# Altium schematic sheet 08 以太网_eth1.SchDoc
size 297 x 209 mm
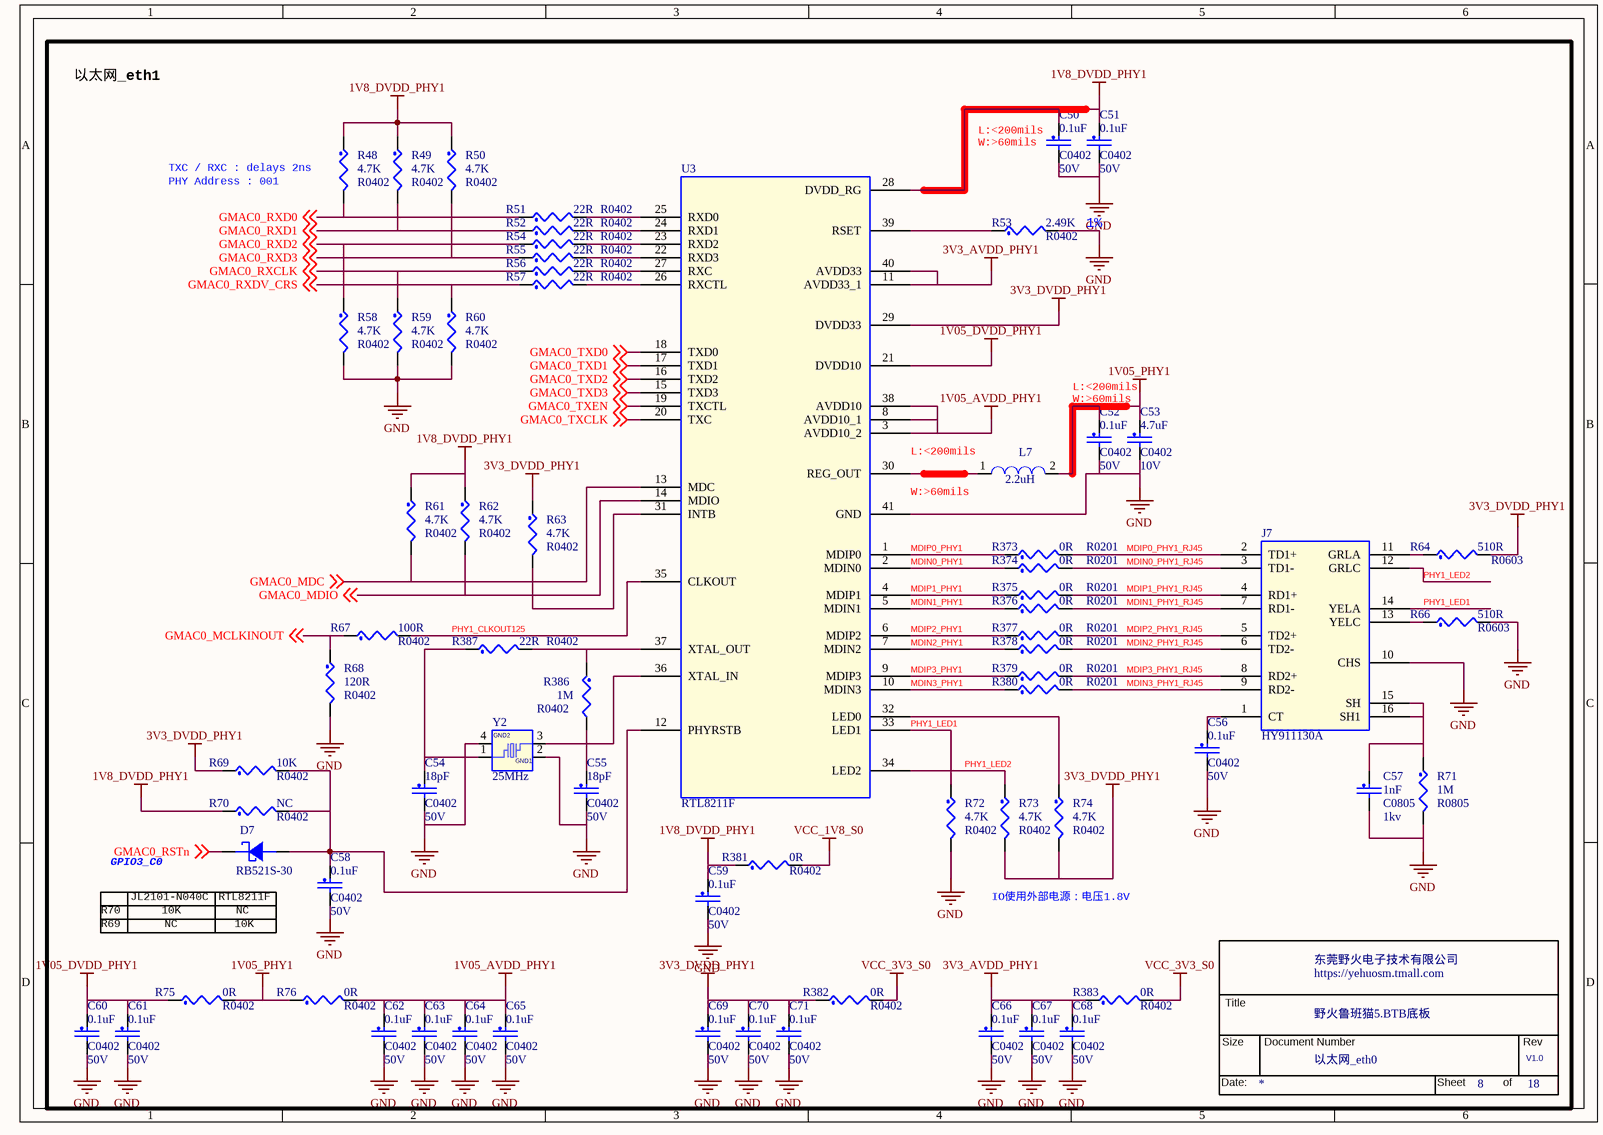
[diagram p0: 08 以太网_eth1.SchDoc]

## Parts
*  Doc: 以太网_eth0  RevCode: V1.0  Title: 野火鲁班猫5.BTB底板  OrgName: 东莞野火电子技术有限公司  Page Number: 8  Page Count: 18  (hidden comment: TitleBlock_YHSCH)  (graphical)
C50  0.1uF  Voltage: 50V  [C0402]
C51  0.1uF  Voltage: 50V  [C0402]
C52  0.1uF  Voltage: 50V  [C0402]
C53  4.7uF  Voltage: 10V  [C0402]
C54  18pF  Voltage: 50V  [C0402]
C55  18pF  Voltage: 50V  [C0402]
C56  0.1uF  Voltage: 50V  [C0402]
C57  1nF  Voltage: 1kv  [C0805]
C58  0.1uF  Voltage: 50V  [C0402]
C59  0.1uF  Voltage: 50V  [C0402]
C60  0.1uF  Voltage: 50V  [C0402]
C61  0.1uF  Voltage: 50V  [C0402]
C62  0.1uF  Voltage: 50V  [C0402]
C63  0.1uF  Voltage: 50V  [C0402]
C64  0.1uF  Voltage: 50V  [C0402]
C65  0.1uF  Voltage: 50V  [C0402]
C66  0.1uF  Voltage: 50V  [C0402]
C67  0.1uF  Voltage: 50V  [C0402]
C68  0.1uF  Voltage: 50V  [C0402]
C69  0.1uF  Voltage: 50V  [C0402]
C70  0.1uF  Voltage: 50V  [C0402]
C71  0.1uF  Voltage: 50V  [C0402]
D7  RB521S-30  [SOD523]
J7  HY911130A  [HY911130A]
L7  2.2uH  [L2520]
R48  4.7K  [R0402]
R49  4.7K  [R0402]
R50  4.7K  [R0402]
R51  22R  [R0402]
R52  22R  [R0402]
R53  2.49K  [R0402]
R54  22R  [R0402]
R55  22R  [R0402]
R56  22R  [R0402]
R57  22R  [R0402]
R58  4.7K  [R0402]
R59  4.7K  [R0402]
R60  4.7K  [R0402]
R61  4.7K  [R0402]
R62  4.7K  [R0402]
R63  4.7K  [R0402]
R64  510R  [R0603]
R66  510R  [R0603]
R67  100R  [R0402]
R68  120R  [R0402]
R69  10K  [R0402]
R70  NC  [R0402]
R71  1M  [R0805]
R72  4.7K  [R0402]
R73  4.7K  [R0402]
R74  4.7K  [R0402]
R75  0R  [R0402]
R76  0R  [R0402]
R373  0R  [R0201]
R374  0R  [R0201]
R375  0R  [R0201]
R376  0R  [R0201]
R377  0R  [R0201]
R378  0R  [R0201]
R379  0R  [R0201]
R380  0R  [R0201]
R381  0R  [R0402]
R382  0R  [R0402]
R383  0R  [R0402]
R386  1M  [R0402]
R387  22R  [R0402]
U3  RTL8211F  [qfp_40p_r]
Y2  25MHz  [3225]

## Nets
1V05_AVDD_PHY1: C62.1 C63.1 C64.1 C65.1 R76.2 U3.3(AVDD10_2) U3.8(AVDD10_1) U3.38(AVDD10)
1V05_DVDD_PHY1: C60.1 C61.1 R75.1 U3.21(DVDD10)
1V05_PHY1: C52.1 C53.1 L7.2 R75.2 R76.1
1V8_DVDD_PHY1: C50.1 C51.1 C59.1 R48.1 R49.1 R50.1 R61.1 R62.1 R70.1 R381.1 U3.28(DVDD_RG)
3V3_AVDD_PHY1: C66.1 C67.1 C68.1 R383.1 U3.11(AVDD33_1) U3.40(AVDD33)
3V3_DVDD_PHY1: C69.1 C70.1 C71.1 R63.1 R64.2 R69.1 R73.2 R74.2 R382.1 U3.29(DVDD33)
GND: C50.2 C51.2 C52.2 C53.2 C54.2 C55.2 C56.2 C57.2 C58.2 C59.2 C60.2 C61.2 C62.2 C63.2 C64.2 C65.2 C66.2 C67.2 C68.2 C69.2 C70.2 C71.2 J7.10(CHS) R53.2 R58.2 R59.2 R60.2 R66.2 R68.2 R71.2 R72.2 U3.41(GND) Y2.2(GND1) Y2.4(GND2)
VCC_1V8_S0: R381.2
VCC_3V3_S0: R382.2 R383.2
GMAC0_MCLKINOUT: R67.1 R68.1 ; off-sheet GMAC0_MCLKINOUT
GMAC0_MDC: R61.2 U3.13(MDC) ; off-sheet GMAC0_MDC
GMAC0_MDIO: R62.2 U3.14(MDIO) ; off-sheet GMAC0_MDIO
GMAC0_RSTn: D7.1 ; off-sheet GMAC0_RSTn
GMAC0_RXCLK: R56.1 R59.1 ; off-sheet GMAC0_RXCLK
GMAC0_RXD0: R48.2 R51.1 ; off-sheet GMAC0_RXD0
GMAC0_RXD1: R49.2 R52.1 ; off-sheet GMAC0_RXD1
GMAC0_RXD2: R54.1 R58.1 ; off-sheet GMAC0_RXD2
GMAC0_RXD3: R50.2 R55.1 ; off-sheet GMAC0_RXD3
GMAC0_RXDV_CRS: R57.1 R60.1 ; off-sheet GMAC0_RXDV_CRS
GMAC0_TXCLK: U3.20(TXC) ; off-sheet GMAC0_TXCLK
GMAC0_TXD0: U3.18(TXD0) ; off-sheet GMAC0_TXD0
GMAC0_TXD1: U3.17(TXD1) ; off-sheet GMAC0_TXD1
GMAC0_TXD2: U3.16(TXD2) ; off-sheet GMAC0_TXD2
GMAC0_TXD3: U3.15(TXD3) ; off-sheet GMAC0_TXD3
GMAC0_TXEN: U3.19(TXCTL) ; off-sheet GMAC0_TXEN
MDIN0_PHY1: R374.1 U3.2(MDIN0)
MDIN0_PHY1_RJ45: J7.3(TD1-) R374.2
MDIN1_PHY1: R376.1 U3.5(MDIN1)
MDIN1_PHY1_RJ45: J7.7(RD1-) R376.2
MDIN2_PHY1: R378.1 U3.7(MDIN2)
MDIN2_PHY1_RJ45: J7.6(TD2-) R378.2
MDIN3_PHY1: R380.1 U3.10(MDIN3)
MDIN3_PHY1_RJ45: J7.9(RD2-) R380.2
MDIP0_PHY1: R373.1 U3.1(MDIP0)
MDIP0_PHY1_RJ45: J7.2(TD1+) R373.2
MDIP1_PHY1: R375.1 U3.4(MDIP1)
MDIP1_PHY1_RJ45: J7.4(RD1+) R375.2
MDIP2_PHY1: R377.1 U3.6(MDIP2)
MDIP2_PHY1_RJ45: J7.5(TD2+) R377.2
MDIP3_PHY1: R379.1 U3.9(MDIP3)
MDIP3_PHY1_RJ45: J7.8(RD2+) R379.2
PHY1_CLKOUT125: R67.2 U3.35(CLKOUT)
PHY1_LED1: J7.14(YELA) R72.1 U3.33(LED1)
PHY1_LED2: J7.12(GRLC) R73.1 U3.34(LED2)
NetC54_1: C54.1 R387.1 Y2.1
NetC55_1: C55.1 R386.2 U3.36(XTAL_IN) Y2.3
NetC56_1: C56.1 J7.1(CT)
NetC57_1: C57.1 J7.15(SH) J7.16(SH1) R71.1
NetC58_1: C58.1 D7.2 R69.2 R70.2 U3.12(PHYRSTB)
NetJ7_11: J7.11(GRLA) R64.1
NetJ7_13: J7.13(YELC) R66.1
NetL7_1: L7.1 U3.30(REG_OUT)
NetR51_2: R51.2 U3.25(RXD0)
NetR52_2: R52.2 U3.24(RXD1)
NetR53_1: R53.1 U3.39(RSET)
NetR54_2: R54.2 U3.23(RXD2)
NetR55_2: R55.2 U3.22(RXD3)
NetR56_2: R56.2 U3.27(RXC)
NetR57_2: R57.2 U3.26(RXCTL)
NetR63_2: R63.2 U3.31(INTB)
NetR74_1: R74.1 U3.32(LED0)
NetR386_1: R386.1 R387.2 U3.37(XTAL_OUT)

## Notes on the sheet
- 以太网_eth1
- (near C50) L:<200mils
  W:>60mils
- PHY Address : 001
- TXC / RXC : delays 2ns
- (near R53) 1%
- L:<200mils
  W:>60mils
- L:<200mils
- W:>60mils
- GPIO3_C0
- R70
- R69
- JL2101-N040C
- 10K
- NC
- (near D7) RTL8211F
- IO使用外部电源：电压1.8V

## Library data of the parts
* = TitleBlock_YHSCH: Cage Code: 1
C50-C52 C59 C66-C68 = CAP_NP: CLASS: DISCRETE; 规格: 贴片电容0.1uF 10% 50V X5R 0402; 规格编号: 0402X104K500NT; 条码: EBF29060118; 品牌: 风华; 类别: 贴片电容0402; 规格书: 风华电容.pdf; 价格: 0.029826; 生命周期: 量产
C53 = CAP_NP: CLASS: DISCRETE; 规格: 贴片电容4.7uF 10% 10V X5R 0402; 规格编号: CC0402KRX5R6BB475; 条码: EBF29060248; 品牌: 国巨; 类别: 贴片电容0402; 规格书: 国巨-贴片电容.pdf; 价格: 0.059058; 生命周期: 量产
C54 C55 = CAP_NP: CLASS: DISCRETE; 规格: 贴片电容18pF 5% 50V C0G 0402; 规格编号: 0402CG180J500NT; 条码: EBF29060235; 品牌: 风华; 类别: 贴片电容0402; 规格书: 风华电容.pdf; 价格: 0.00515; 生命周期: 量产
C56 C58 C60-C65 C69-C71 = CAP_NP: CLASS: DISCRETE; 生命周期: 量产; 价格: 0.029826; 规格书: 风华电容.pdf; 类别: 贴片电容0402; 品牌: 风华; 条码: EBF29060118; 规格编号: 0402X104K500NT; 规格: 贴片电容0.1uF 10% 50V X5R 0402
C57 = CAP_NP: CLASS: DISCRETE; 生命周期: 量产; 价格: 0.083527; 规格书: 华新科0805系列高压贴片电容.pdf; 类别: 贴片电容0805; 品牌: 华新科; 条码: EBF29060304; 规格编号: 0805B102K102CT; 规格: 贴片电容1nF 10% 1kV X7R 0805
D7 = DIODE_SCHTKY: CLASS: IC; 生命周期: 量产; 价格: 0.06781; 规格书: 江苏长电_RB521S-30.pdf; 类别: 贴片肖特基二极管; 品牌: 江苏长电; 条码: EBFCIS221114153437; 规格: 直流反向耐压(Vr)：30V 平均整流电流(Io)：200mA 正向压降(Vf)：500mV@200mA 30V@100mA,VF=350mV@10mA
J7 = HY911130A: 规格: 屏蔽式以太网连接器RJ45 引脚数14 LED灯黄绿 1000M; 条码: EBF29040053; 品牌: 汉仁; 类别: 网口; 规格书: 汉仁_1000M_ HY911130A.pdf; 价格: 11.12; 生命周期: 量产
L7 = IND: CLASS: DISCRETE; 规格: 功率电感2.2uH 2.2uH ±20% 2.06A 85mΩ; 规格编号: WIP252012P-2R2ML; 条码: EBFCIS220927171910; 品牌: 佳邦; 类别: 贴片电感2520; 规格书: 佳邦_ WIP252012P-2R2ML.pdf; 价格: 0.129914; 生命周期: 量产
R48-R50 R58-R63 R72-R74 = RES: CLASS: DISCRETE; 规格: 贴片电阻4.7K 1% 1/16W 0402; 规格编号: RI0402L4701FT; 条码: EBF29070047; 品牌: 合科泰; 类别: 贴片电阻0402; 规格书: 合科泰-RI系列电阻.pdf; 生命周期: 量产
R51 R52 R54-R57 = RES: CLASS: DISCRETE; 生命周期: 量产; 规格书: 合科泰-RI系列电阻.pdf; 类别: 贴片电阻0402; 品牌: 合科泰; 条码: EBF29070181; 规格编号: RI0402L22R0FT; 规格: 贴片电阻22R 1% 1/16W 0402
R53 = RES: CLASS: DISCRETE; 价格: 0.004709; 生命周期: 量产; 规格书: 厚声-无铅厚膜电阻.pdf; 类别: 贴片电阻0402; 品牌: 厚声; 条码: EBF29070292; 规格编号: 0402WGF2491TCE; 规格: 贴片电阻2.49K 1% 1/16W 0402
R64 = RES: CLASS: DISCRETE; 规格: 贴片电阻510R 1% 1/10W 0603; 规格编号: RI0603L5100FT; 条码: EBF29070091; 品牌: 合科泰; 类别: 贴片电阻0603; 规格书: 合科泰-RI系列电阻.pdf; 生命周期: 量产
R66 = RES: CLASS: DISCRETE; 生命周期: 量产; 规格书: 合科泰-RI系列电阻.pdf; 类别: 贴片电阻0603; 品牌: 合科泰; 条码: EBF29070091; 规格编号: RI0603L5100FT; 规格: 贴片电阻510R 1% 1/10W 0603
R67 = RES: CLASS: DISCRETE; 生命周期: 量产; 规格书: 合科泰-RI系列电阻.pdf; 类别: 贴片电阻0402; 品牌: 合科泰; 条码: EBF29070053; 规格编号: RI0402L1000FT; 规格: 贴片电阻100R 1% 1/16W 0402
R68 = RES: CLASS: DISCRETE; 生命周期: 量产; 规格书: 厚声-无铅厚膜电阻.pdf; 类别: 贴片电阻0402; 品牌: 厚声; 条码: EBF29070275; 规格编号: 0402WGF1200TCE; 规格: 贴片电阻120R 1% 1/16W 0402; 价格: 0.002198
R69 = RES: CLASS: DISCRETE; 生命周期: 量产; 价格: 0.002773; 规格书: 厚声-无铅厚膜电阻.pdf; 类别: 贴片电阻0402; 品牌: 厚声; 条码: EBF29070046; 规格编号: 0402WGF1002TCE; 规格: 贴片电阻10K 1% 1/16W 0402
R70 = RES: CLASS: DISCRETE; 规格: 贴片电阻NC 预留; 条码: EBF29070087; 类别: 贴片电阻0402
R71 = RES: CLASS: DISCRETE; 生命周期: 量产; 价格: 0.02396; 规格书: YAGEO国巨厚膜无铅电阻.pdf; 类别: 贴片电阻0805; 品牌: 国巨; 条码: EBF29070294; 规格编号: AC0805FR-071ML; 规格: 贴片电阻1M 1% 1/8W 0805
R75 R76 R381 R382 = RES: CLASS: DISCRETE; 生命周期: 量产; 规格书: 合科泰-RI系列电阻.pdf; 类别: 贴片电阻0402; 品牌: 合科泰; 条码: EBF29070049; 规格编号: RI0402L000FT; 规格: 贴片电阻0R 1% 1/16W 0402
R373-R380 = RES: CLASS: DISCRETE; 规格: 贴片电阻0R 1% 1/20W 0201; 规格编号: RI0201L0000FT; 条码: EBF29070164; 品牌: 合科泰; 类别: 贴片电阻0201; 规格书: 合科泰-RI系列电阻.pdf; 生命周期: 量产
R383 = RES: CLASS: DISCRETE; 规格: 贴片电阻0R 1% 1/16W 0402; 规格编号: RI0402L000FT; 条码: EBF29070049; 品牌: 合科泰; 类别: 贴片电阻0402; 规格书: 合科泰-RI系列电阻.pdf; 生命周期: 量产
R386 = RES: CLASS: DISCRETE; 生命周期: 量产; 规格书: 合科泰-RI系列电阻.pdf; 类别: 贴片电阻0402; 品牌: 厚声; 条码: EBF29070062; 规格编号: RI0402L1004FT; 规格: 贴片电阻1M 1% 1/16W 0402
R387 = RES: CLASS: DISCRETE; 规格: 贴片电阻22R 1% 1/16W 0402; 规格编号: RI0402L22R0FT; 条码: EBF29070181; 品牌: 合科泰; 类别: 贴片电阻0402; 规格书: 合科泰-RI系列电阻.pdf; 生命周期: 量产
U3 = RTL8211F: 价格: 15.2; 生命周期: 量产; 规格书: 瑞昱_RTL8211F-CG.pdf; 类别: 以太网芯片; 品牌: 瑞昱; 条码: EBF29150018; 规格编号: RTL8211F-CG; 规格: 以太网芯片 10M/100M/1000M 控制接口：RGMII RGMII电压：3.3V/2.5V/1.8V/1.5V
Y2 = CRYSTAL_4P: CLASS: IC; 规格: 无源晶振25MHZ 50Ω 16pF 3225; 规格编号: X322525MQB4SI; 条码: EBF29100005; 品牌: 扬兴科技; 类别: 贴片晶振 3225; 规格书: 扬兴科技-25MHZ.pdf; 价格: 0.385846; 生命周期: 量产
